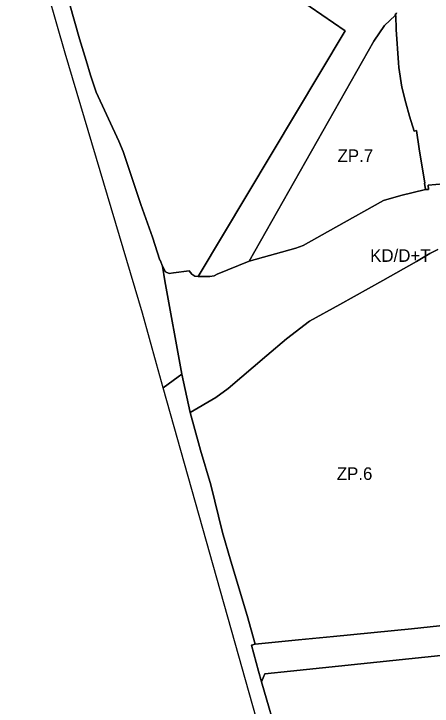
# Model space of a CAD drawing. Extents: x 7423367 to 7424726, y 5546744 to 5548391.
# Drawn here: x 7423559.3 to 7423725.3, y 5547370 to 5547645 of the extents above; entities that cross this region are included whole.
import ezdxf

# ---------------------------------------------------------------- set-up
doc = ezdxf.new("R2010")
doc.units = 0
doc.layers.add('linie_rozgraniczajace', color=7, linetype='Continuous')
doc.layers.add('oznaczenia_przeznaczen', color=7, linetype='Continuous')

msp = doc.modelspace()

# ---------------------------------------------------------------- linework, layer by layer
at = {"layer": 'linie_rozgraniczajace'}
for points in [[(7423581.32, 5547649.09), (7423585.34, 5547634.98), (7423587.96, 5547626.39), (7423589.64, 5547620.62), (7423591.96, 5547613.8), (7423600.97, 5547594.38), (7423602.62, 5547590.26), (7423603.95, 5547586.3), (7423609.73, 5547569.22), (7423614.25, 5547556.31), (7423617.25, 5547547.18), (7423617.28, 5547547.09), (7423618.29, 5547544.68), (7423619.25, 5547538.87), (7423625.9, 5547501.81), (7423624.51, 5547500.77), (7423618.57, 5547496.4), (7423615.92, 5547506), (7423610.38, 5547526.05), (7423579.63, 5547629.35), (7423559.28, 5547700.42)], [(7423616.68, 5547689.14), (7423690.72, 5547638.24), (7423632.39, 5547540.59), (7423631.15, 5547540.81), (7423629.92, 5547541.55), (7423628.86, 5547542.88), (7423622.61, 5547542.02), (7423620.87, 5547541.76), (7423619.44, 5547542.42), (7423618.29, 5547544.68), (7423617.28, 5547547.09), (7423617.25, 5547547.18), (7423614.25, 5547556.31), (7423609.73, 5547569.22), (7423603.95, 5547586.3), (7423602.62, 5547590.26), (7423600.97, 5547594.38), (7423591.96, 5547613.8), (7423589.64, 5547620.62), (7423587.96, 5547626.39), (7423585.34, 5547634.98), (7423581.32, 5547649.09)], [(7423711.07, 5547645.3), (7423711.02, 5547644.88), (7423710.7, 5547644.94), (7423710.59, 5547644.29), (7423706.42, 5547640.35), (7423702.15, 5547634.15), (7423652.6, 5547546.77), (7423640.02, 5547541.56), (7423638.8, 5547540.89), (7423637.11, 5547540.59), (7423632.39, 5547540.59), (7423690.72, 5547638.24), (7423616.68, 5547689.14)], [(7423732.75, 5547577.68), (7423723.64, 5547576.96), (7423723.81, 5547575.25), (7423722.63, 5547575.13), (7423722.22, 5547577.72), (7423722.32, 5547577.75), (7423720.11, 5547591.34), (7423719.07, 5547598.64), (7423718.07, 5547598.4), (7423716.34, 5547604.34), (7423714.81, 5547609.55), (7423713.21, 5547615.86), (7423712.07, 5547623.63), (7423711.85, 5547625.56), (7423710.99, 5547638.74), (7423710.84, 5547644.24), (7423710.59, 5547644.29), (7423710.7, 5547644.94), (7423711.02, 5547644.88), (7423711.07, 5547645.3)], [(7423727.47, 5547551.35), (7423724.4, 5547549.81), (7423719.1, 5547546.59), (7423705.69, 5547539.01), (7423688.62, 5547529.55), (7423676.65, 5547522.84), (7423667.44, 5547515.81), (7423659.68, 5547509.22), (7423644.37, 5547496.15), (7423639.45, 5547492.59), (7423629.24, 5547486.67), (7423625.9, 5547501.81), (7423619.25, 5547538.87), (7423618.29, 5547544.68), (7423619.44, 5547542.42), (7423620.87, 5547541.76), (7423622.61, 5547542.02), (7423628.86, 5547542.88), (7423629.92, 5547541.55), (7423631.15, 5547540.81), (7423632.39, 5547540.59), (7423637.11, 5547540.59), (7423638.8, 5547540.89), (7423640.02, 5547541.56), (7423652.6, 5547546.77), (7423671.2, 5547551.92), (7423674.02, 5547552.93), (7423686.98, 5547560.21), (7423705.9, 5547570.82), (7423712.83, 5547572.86), (7423722.63, 5547575.13), (7423723.81, 5547575.25), (7423723.64, 5547576.96), (7423732.75, 5547577.68)], [(7423735.54, 5547402.61), (7423717.1, 5547400.73), (7423686.16, 5547397.62), (7423672.23, 5547396.35), (7423655.02, 5547394.63), (7423651.85, 5547405.92), (7423645.37, 5547427.61), (7423642.08, 5547438.94), (7423637.46, 5547457.86), (7423633.3, 5547471.66), (7423632.93, 5547473.14), (7423629.24, 5547486.67), (7423639.45, 5547492.59), (7423644.37, 5547496.15), (7423659.68, 5547509.22), (7423667.44, 5547515.81), (7423676.65, 5547522.84), (7423688.62, 5547529.55), (7423705.69, 5547539.01), (7423719.1, 5547546.59), (7423724.4, 5547549.81), (7423727.47, 5547551.35)], [(7423655.54, 5547364.92), (7423618.57, 5547496.4), (7423624.51, 5547500.77), (7423625.9, 5547501.81), (7423629.24, 5547486.67), (7423632.93, 5547473.14), (7423633.3, 5547471.66), (7423637.46, 5547457.86), (7423642.08, 5547438.94), (7423645.37, 5547427.61), (7423651.85, 5547405.92), (7423655.02, 5547394.63), (7423653.58, 5547394.22), (7423656.39, 5547383.88), (7423657.58, 5547379.7), (7423664.51, 5547355.5)], [(7423756.67, 5547393.03), (7423669.04, 5547383.82), (7423658.91, 5547382.75), (7423657.58, 5547379.7), (7423656.39, 5547383.88), (7423653.58, 5547394.22), (7423655.02, 5547394.63), (7423672.23, 5547396.35), (7423686.16, 5547397.62), (7423717.1, 5547400.73), (7423735.54, 5547402.61)], [(7423664.51, 5547355.5), (7423657.58, 5547379.7), (7423658.91, 5547382.75), (7423669.04, 5547383.82), (7423756.67, 5547393.03), (7423757.63, 5547387.95), (7423757.71, 5547387.52), (7423775.28, 5547304.1)]]:
    msp.add_lwpolyline(points, dxfattribs=at)
msp.add_lwpolyline([(7423652.6, 5547546.77), (7423702.15, 5547634.15), (7423706.42, 5547640.35), (7423710.59, 5547644.29), (7423710.84, 5547644.24), (7423710.99, 5547638.74), (7423711.85, 5547625.56), (7423712.07, 5547623.63), (7423713.21, 5547615.86), (7423714.81, 5547609.55), (7423716.34, 5547604.34), (7423718.07, 5547598.4), (7423719.07, 5547598.64), (7423720.11, 5547591.34), (7423722.32, 5547577.75), (7423722.22, 5547577.72), (7423722.63, 5547575.13), (7423712.83, 5547572.86), (7423705.9, 5547570.82), (7423686.98, 5547560.21), (7423674.02, 5547552.93), (7423671.2, 5547551.92)], close=True, dxfattribs=at)

# ---------------------------------------------------------------- texts
at = {"layer": 'oznaczenia_przeznaczen'}
for s, p in [('ZP.7', (7423687.72, 5547586.1)), ('KD/D+T', (7423700.67, 5547546.45)), ('ZP.6', (7423687.43, 5547459.83))]:
    msp.add_text(s, height=5, dxfattribs=at).set_placement(p)

doc.saveas('drawing.dxf')
